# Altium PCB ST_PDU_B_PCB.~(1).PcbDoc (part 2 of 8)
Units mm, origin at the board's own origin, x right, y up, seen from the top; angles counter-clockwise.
Board outline 200 x 200 mm, 6 copper layers (Top Layer, Layer 1, Layer 2, Layer 3, Layer 4, Bottom Layer), stack 3.194 mm thick; 894 components, 723 nets, 3233 pads, 4067 vias.
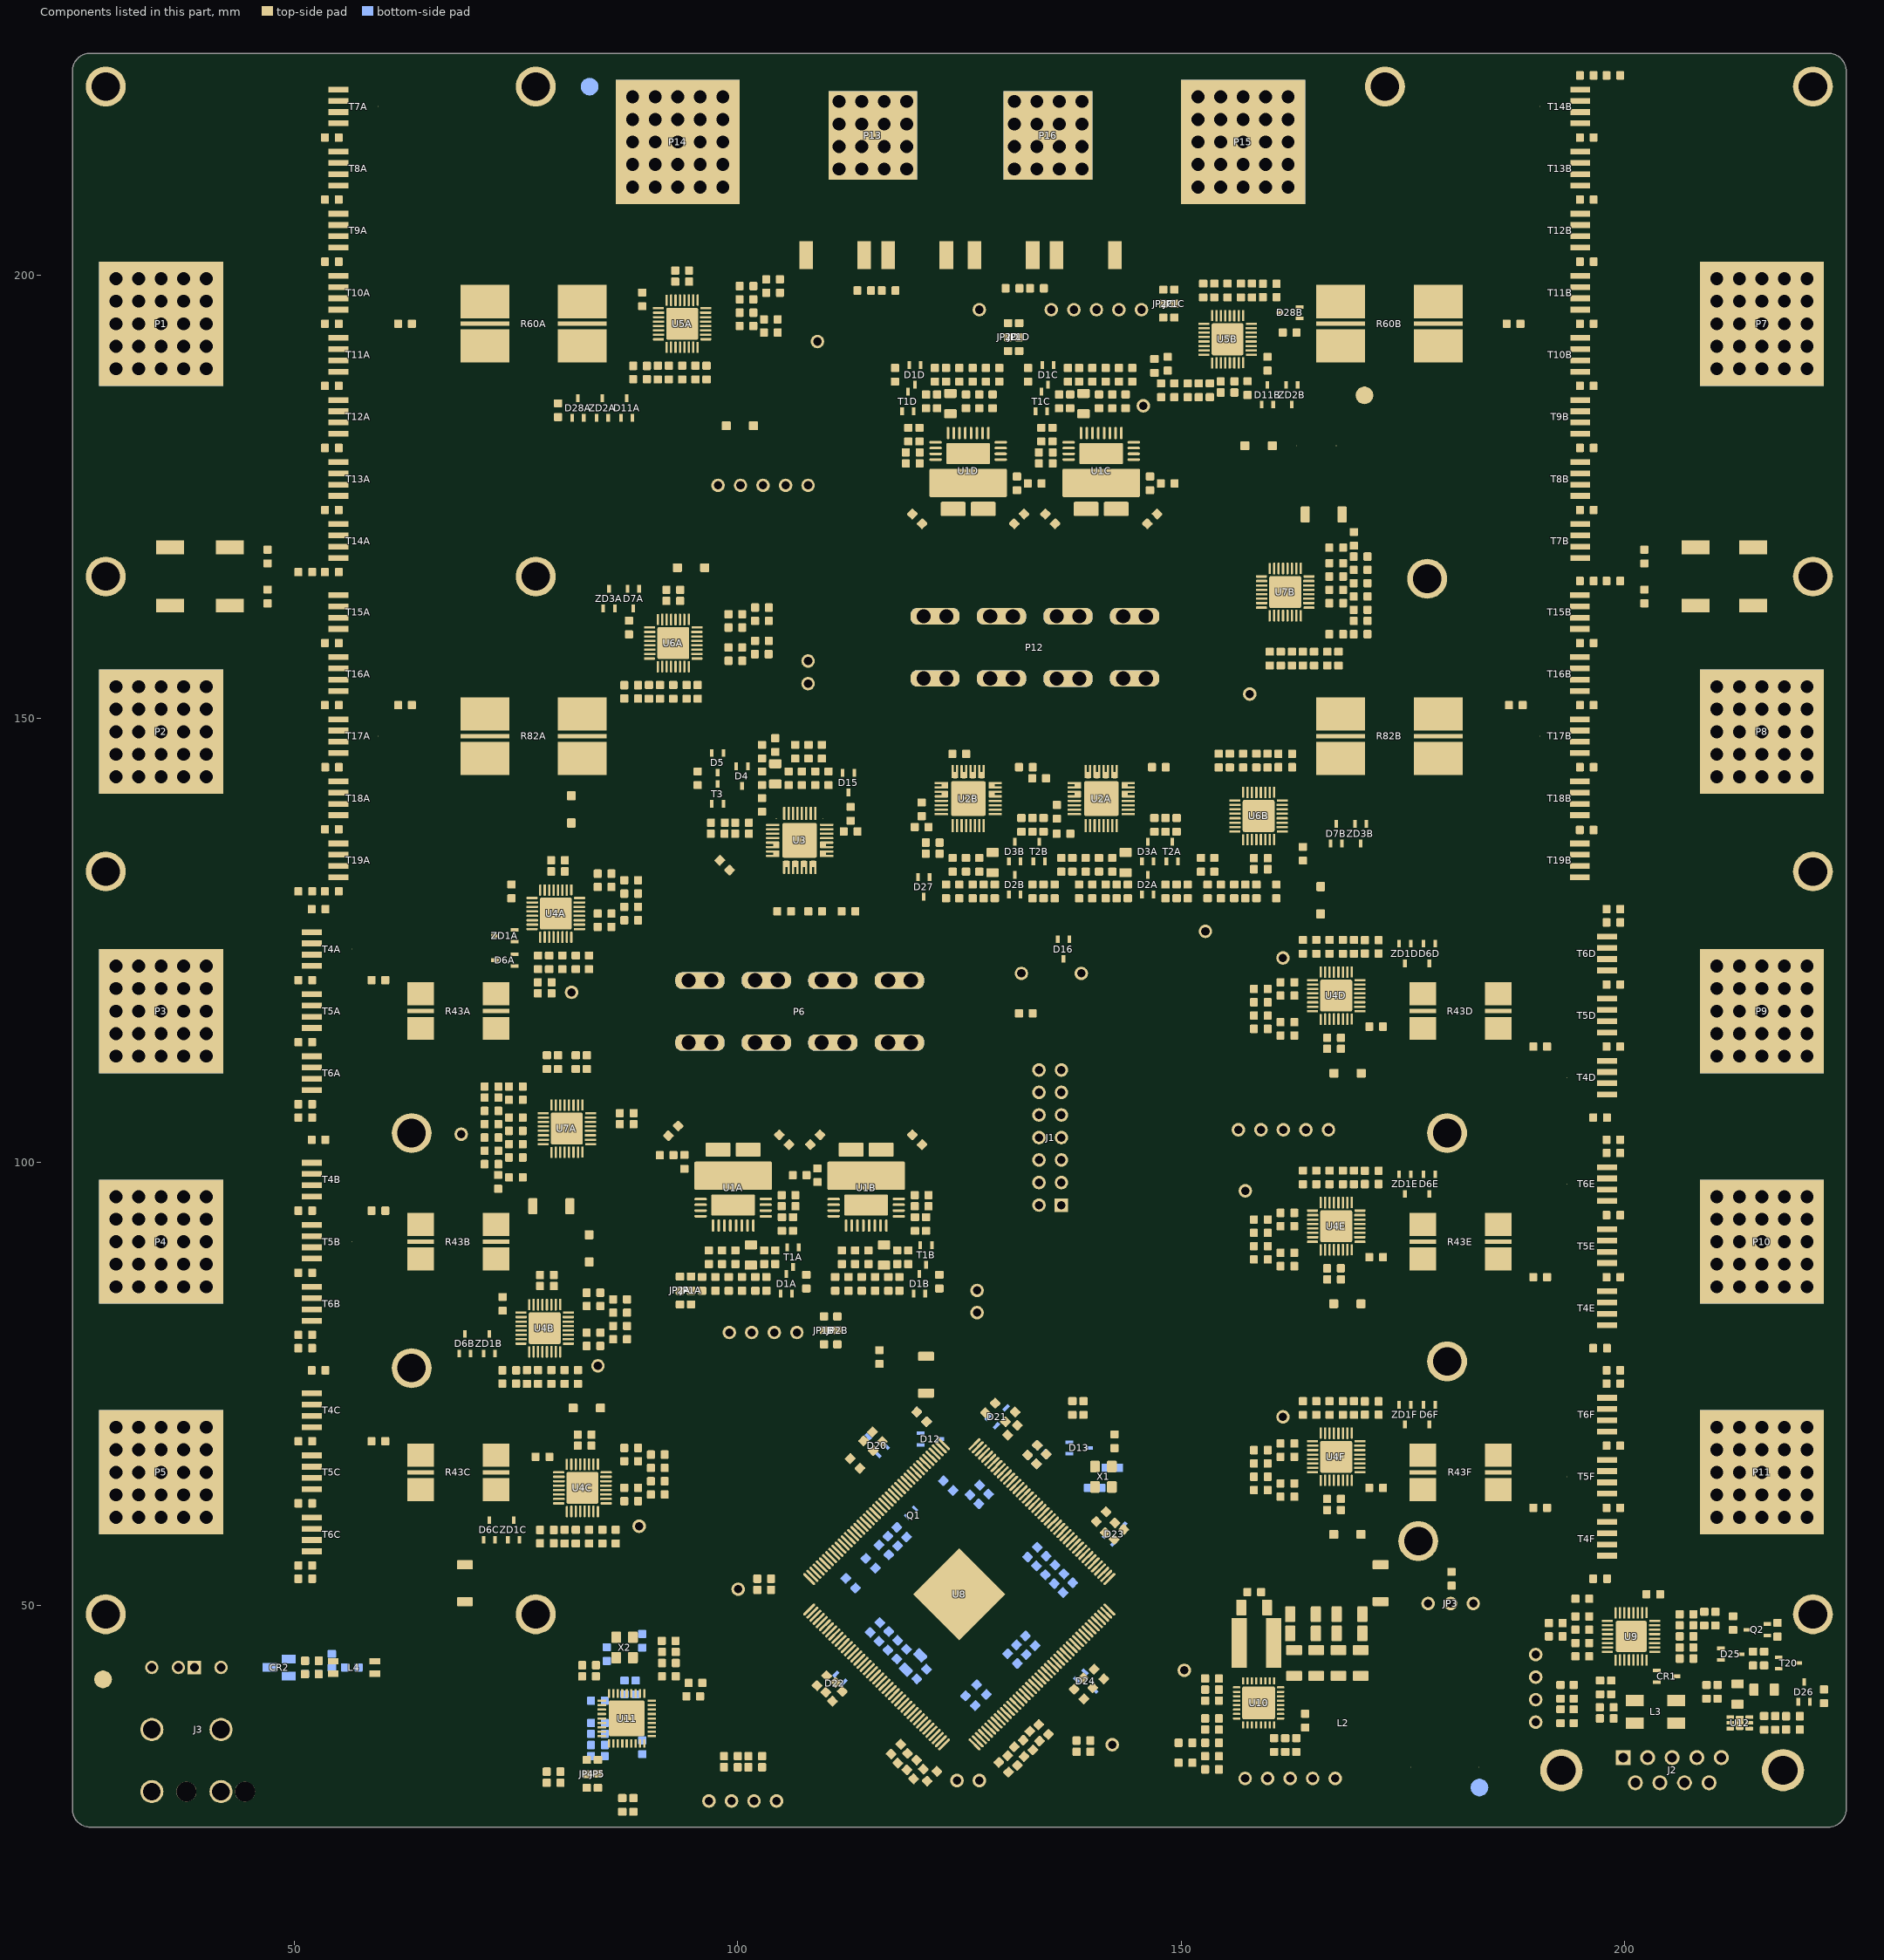
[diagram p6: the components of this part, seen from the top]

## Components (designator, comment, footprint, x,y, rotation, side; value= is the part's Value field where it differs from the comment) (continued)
R48D "2k7" R0603_round 162,120.25 r180 top (schematic designator R48)
R48E "2k7" R0603_round 162,94.25 r180 top (schematic designator R48)
R48F "2k7" R0603_round 162,68.25 r180 top (schematic designator R48)
R49A "5k6" R0603_round 88,127.25 r0 top (schematic designator R49)
R49B "5k6" R0603_round 86.75,80 r0 top (schematic designator R49)
R49C "5k6" R0603_round 91,62.5 r0 top (schematic designator R49)
R49D "5k6" R0603_round 159,119.5 r180 top (schematic designator R49)
R49E "5k6" R0603_round 159,93.5 r180 top (schematic designator R49)
R49F "5k6" R0603_round 159,67.5 r180 top (schematic designator R49)
R50A "180R" R0603_round 85,128 r180 top (schematic designator R50)
R50B "180R" R0603_round 83.75,80.75 r180 top (schematic designator R50)
R50C "180R" R0603_round 88,63.25 r180 top (schematic designator R50)
R50D "180R" R0603_round 162,118.75 r0 top (schematic designator R50)
R50E "180R" R0603_round 162,92.75 r0 top (schematic designator R50)
R50F "180R" R0603_round 162,66.75 r0 top (schematic designator R50)
R51A "5k6" R0603_round 88,128.75 r0 top (schematic designator R51)
R51B "5k6" R0603_round 86.75,81.5 r0 top (schematic designator R51)
R51C "5k6" R0603_round 91,64 r0 top (schematic designator R51)
R51D "5k6" R0603_round 159,118 r180 top (schematic designator R51)
R51E "5k6" R0603_round 159,92 r180 top (schematic designator R51)
R51F "5k6" R0603_round 159,66 r180 top (schematic designator R51)
R52 "15k" R0603_round 150.5,32.25 r180 top
R53A "1R" R0603_round 51.25,106.5 r180 top (schematic designator R53)
R53B "1R" R0603_round 51.25,80.5 r180 top (schematic designator R53)
R53C "1R" R0603_round 51.25,54.5 r180 top (schematic designator R53)
R53D "1R" R0603_round 198.75,127 r0 top (schematic designator R53)
R53E "1R" R0603_round 198.75,101 r0 top (schematic designator R53)
R53F "1R" R0603_round 198.75,75 r0 top (schematic designator R53)
R54A "NTC" R0603_round 59.5,120.5 r180 top value="NTC, 10K" (schematic designator R54)
R54B "NTC" R0603_round 59.5,94.5 r180 top value="NTC, 10K" (schematic designator R54)
R54C "NTC" R0603_round 59.5,68.5 r180 top value="NTC, 10K" (schematic designator R54)
R54D "NTC" R0603_round 190.5,113 r0 top value="NTC, 10K" (schematic designator R54)
R54E "NTC" R0603_round 190.5,87 r0 top value="NTC, 10K" (schematic designator R54)
R54F "NTC" R0603_round 190.5,61 r0 top value="NTC, 10K" (schematic designator R54)
R55A "47k" R0603_round 85,131 r180 top (schematic designator R55)
R55B "47k" R0603_round 83.75,83.75 r180 top (schematic designator R55)
R55C "47k" R0603_round 88,66.25 r180 top (schematic designator R55)
R55D "47k" R0603_round 162,115.75 r0 top (schematic designator R55)
R55E "47k" R0603_round 162,89.75 r0 top (schematic designator R55)
R55F "47k" R0603_round 162,63.75 r0 top (schematic designator R55)
R56A "10k" R0603_round 74.5,130.5 r270 top (schematic designator R56)
R56B "10k" R0603_round 73.5,84 r270 top (schematic designator R56)
R56C "10k" R0603_round 78,66.75 r180 top (schematic designator R56)
R56D "10k" R0603_round 172,115.25 r0 top (schematic designator R56)
R56E "10k" R0603_round 172,89.25 r0 top (schematic designator R56)
R56F "10k" R0603_round 172,63.25 r0 top (schematic designator R56)
R57A "2k7" R0603_round 88,130.25 r0 top (schematic designator R57)
R57B "2k7" R0603_round 86.75,83 r0 top (schematic designator R57)
R57C "2k7" R0603_round 91,65.5 r0 top (schematic designator R57)
R57D "2k7" R0603_round 159,116.5 r180 top (schematic designator R57)
R57E "2k7" R0603_round 159,90.5 r180 top (schematic designator R57)
R57F "2k7" R0603_round 159,64.5 r180 top (schematic designator R57)
R58A "2k7" R0603_round 88,131.75 r0 top (schematic designator R58)
R58B "2k7" R0603_round 86.75,84.5 r0 top (schematic designator R58)
R58C "2k7" R0603_round 91,67 r0 top (schematic designator R58)
R58D "2k7" R0603_round 159,115 r180 top (schematic designator R58)
R58E "2k7" R0603_round 159,89 r180 top (schematic designator R58)
R58F "2k7" R0603_round 159,63 r180 top (schematic designator R58)
R59A "2k7" R0603_round 85,132.5 r0 top (schematic designator R59)
R59B "2k7" R0603_round 83.75,85.25 r0 top (schematic designator R59)
R59C "2k7" R0603_round 88,67.75 r0 top (schematic designator R59)
R59D "2k7" R0603_round 162,114.25 r180 top (schematic designator R59)
R59E "2k7" R0603_round 162,88.25 r180 top (schematic designator R59)
R59F "2k7" R0603_round 162,62.25 r180 top (schematic designator R59)
R60A "0R0001" "R Shunt 5930" 77,194.5 r0 top (schematic designator R60)
R60B "0R0001" "R Shunt 5930" 173.5,194.5 r180 top (schematic designator R60)
R61A "1R" R0603_round 54.25,215.5 r180 top (schematic designator R61)
R61B "1R" R0603_round 195.75,173.5 r0 top (schematic designator R61)
R62A "1R" R0603_round 54.25,208.5 r180 top (schematic designator R62)
R62B "1R" R0603_round 195.75,180.5 r0 top (schematic designator R62)
R63A "1R" R0603_round 54.25,201.5 r180 top (schematic designator R63)
R63B "1R" R0603_round 195.75,187.5 r0 top (schematic designator R63)
R64A "47k" R0603_round 51.25,166.5 r180 top (schematic designator R64)
R64B "47k" R0603_round 198.75,222.5 r0 top (schematic designator R64)
R65 "15k" R0603_round 153.5,31.5 r180 top
R66A "1R" R0603_round 54.25,194.5 r180 top (schematic designator R66)
R66B "1R" R0603_round 195.75,194.5 r0 top (schematic designator R66)
R67A "2k7" R0603_round 103.75,193.5 r0 top (schematic designator R67)
R67B "2k7" R0603_round 147,189.75 r270 top (schematic designator R67)
R68A "5k6" R0603_round 101,194.25 r0 top (schematic designator R68)
R68B "5k6" R0603_round 147.75,187 r270 top (schematic designator R68)
R69A "180R" R0603_round 103.75,195 r180 top (schematic designator R69)
R69B "180R" R0603_round 148.5,190 r90 top (schematic designator R69)
R70A "5k6" R0603_round 101,195.75 r0 top (schematic designator R70)
R70B "5k6" R0603_round 149.25,187 r270 top (schematic designator R70)
R71 "0R" R0603_round 180.5,53 r270 top
R72A "1R" R0603_round 54.25,187.5 r180 top (schematic designator R72)
R72B "1R" R0603_round 195.75,201.5 r0 top (schematic designator R72)
R73A "NTC" R0603_round 62.5,194.5 r180 top value="NTC, 10K" (schematic designator R73)
R73B "NTC" R0603_round 187.5,194.5 r0 top value="NTC, 10K" (schematic designator R73)
R74A "1R" R0603_round 54.25,180.5 r180 top (schematic designator R74)
R74B "1R" R0603_round 195.75,208.5 r0 top (schematic designator R74)
R75A "47k" R0603_round 101,198.75 r180 top (schematic designator R75)
R75B "47k" R0603_round 152,187 r90 top (schematic designator R75)
R76A "10k" R0603_round 89.25,197.25 r270 top (schematic designator R76)
R76B "10k" R0603_round 159.75,190 r90 top (schematic designator R76)
R77A "2k7" R0603_round 101,197.25 r0 top (schematic designator R77)
R77B "2k7" R0603_round 150.75,187 r270 top (schematic designator R77)
R78A "2k7" R0603_round 104,198 r0 top (schematic designator R78)
R78B "2k7" R0603_round 153.25,187 r270 top (schematic designator R78)
R79A "1R" R0603_round 54.25,173.5 r180 top (schematic designator R79)
R79B "1R" R0603_round 195.75,215.5 r0 top (schematic designator R79)
R80A "2k7" R0603_round 104,199.5 r0 top (schematic designator R80)
R80B "2k7" R0603_round 157.5,187.25 r270 top (schematic designator R80)
R81A "1R" R0603_round 54.25,166.5 r180 top (schematic designator R81)
R81B "1R" R0603_round 195.75,222.5 r0 top (schematic designator R81)
R82A "0R0002" "R Shunt 5930" 77,148 r0 top (schematic designator R82)
R82B "0R0002" "R Shunt 5930" 173.5,148 r180 top (schematic designator R82)
R83A "1R" R0603_round 54.25,158.5 r180 top (schematic designator R83)
R83B "1R" R0603_round 195.75,165.5 r0 top (schematic designator R83)
R84A "47k" R0603_round 51.25,130.5 r180 top (schematic designator R84)
R84B "47k" R0603_round 198.75,165.5 r0 top (schematic designator R84)
R85 "10k" R0603_round 203.25,51.25 r0 top
R86A "1R" R0603_round 54.25,151.5 r180 top (schematic designator R86)
R86B "1R" R0603_round 195.75,158.5 r0 top (schematic designator R86)
R87A "2k7" R0603_round 99.75,156.5 r0 top (schematic designator R87)
R87B "2k7" R0603_round 152.25,133.5 r270 top (schematic designator R87)
R88A "5k6" R0603_round 102.725,157.25 r0 top (schematic designator R88)
R88B "5k6" R0603_round 153,130.5 r270 top (schematic designator R88)
R89A "180R" R0603_round 99.75,158 r180 top (schematic designator R89)
R89B "180R" R0603_round 153.75,133.5 r90 top (schematic designator R89)
R90A "5k6" R0603_round 102.75,158.75 r0 top (schematic designator R90)
R90B "5k6" R0603_round 154.5,130.5 r270 top (schematic designator R90)
R91 "10k" R0603_round 160.5,34.25 r90 top
R92A "1R" R0603_round 54.275,144.5 r180 top (schematic designator R92)
R92B "1R" R0603_round 195.75,151.5 r0 top (schematic designator R92)
R93A "NTC" R0603_round 62.5,151.5 r180 top value="NTC, 10K" (schematic designator R93)
R93B "NTC" R0603_round 187.75,151.5 r0 top value="NTC, 10K" (schematic designator R93)
R94A "47k" R0603_round 99.75,161.75 r180 top (schematic designator R94)
R94B "47k" R0603_round 158.5,130.5 r90 top (schematic designator R94)
R95A "1R" R0603_round 54.25,137.5 r180 top (schematic designator R95)
R95B "1R" R0603_round 195.75,144.5 r0 top (schematic designator R95)
R96A "10k" R0603_round 87.75,160.25 r270 top (schematic designator R96)
R96B "10k" R0603_round 163.749,134.749 r90 top (schematic designator R96)
R97A "2k7" R0603_round 99.75,160.25 r0 top (schematic designator R97)
R97B "2k7" R0603_round 156,130.5 r270 top (schematic designator R97)
R98A "2k7" R0603_round 102.75,161 r0 top (schematic designator R98)
R98B "2k7" R0603_round 157.25,130.5 r270 top (schematic designator R98)
R99A "2k7" R0603_round 102.75,162.5 r0 top (schematic designator R99)
R99B "2k7" R0603_round 160.75,130.5 r270 top (schematic designator R99)
R100A "1R" R0603_round 54.25,130.5 r180 top (schematic designator R100)
R100B "1R" R0603_round 195.736,137.423 r0 top (schematic designator R100)
R101A "330R" R0603_round 72.25,108.5 r180 top (schematic designator R101)
R101B "330R" R0603_round 170.25,159.5 r0 top (schematic designator R101)
R102A "2k7" R0603_round 75,107 r180 top (schematic designator R102)
R102B "2k7" R0603_round 165,156.75 r270 top (schematic designator R102)
R103A "2k7" R0603_round 75,102 r180 top (schematic designator R103)
R103B "2k7" R0603_round 167.5,166 r0 top (schematic designator R103)
R104A "2k7" R0603_round 72.25,101.25 r180 top (schematic designator R104)
R104B "2k7" R0603_round 170.25,166.75 r0 top (schematic designator R104)
R105A "2k7" R0603_round 75,100.5 r180 top (schematic designator R105)
R105B "2k7" R0603_round 167.5,167.5 r0 top (schematic designator R105)
R106A "2k7" R0603_round 72.25,99.75 r180 top (schematic designator R106)
R106B "2k7" R0603_round 170.25,168.25 r0 top (schematic designator R106)
R107A "2k7" R0603_round 75,105 r180 top (schematic designator R107)
R107B "2k7" R0603_round 167.5,163 r0 top (schematic designator R107)
R108A "5k6" R0603_round 72.25,102.75 r180 top (schematic designator R108)
R108B "5k6" R0603_round 170.25,165.25 r0 top (schematic designator R108)
R109A "5k6" R0603_round 72.25,104.25 r180 top (schematic designator R109)
R109B "5k6" R0603_round 170.25,163.75 r0 top (schematic designator R109)
R110A "180R" R0603_round 75,103.5 r180 top (schematic designator R110)
R110B "180R" R0603_round 167.5,164.5 r0 top (schematic designator R110)
R111 "0R" R0603_round 83,111.25 r270 top
R112 "0R" R0603_round 81.75,111.25 r270 top
R113 "0R" R0603_round 79.75,111.25 r270 top
R114 "0R" R0603_round 78.5,111.25 r270 top
R115 "0R" R0603_round 160,156.75 r90 top
R116 "0R" R0603_round 161.25,156.75 r90 top
R117 "0R" R0603_round 162.5,156.75 r90 top
R118 "0R" R0603_round 163.75,156.75 r90 top
R119 "47R" R0603_round 113.25,66 r135 top
R120 "47R" R0603_round 114.75,68 r135 top
R121 "47R" R0603_round 115.75,69 r135 top
R122 "47k" R0603_round 120.75,71.25 r135 bottom
R123 "15k" R0603_round 120.75,71.25 r135 top
R124 "47R" R0603_round 128.5,72.25 r45 top
R125 "47R" R0603_round 130.75,71.25 r45 top
R126 "47R" R0603_round 131,69.75 r45 top
R127 "4k7" R0603_round 133.25,67.5 r45 bottom
R128 "47k" R0603_round 134.239,66.511 r45 bottom
R129 "15k" R0603_round 133.25,67.5 r45 top
R130 "15k" R0603_round 134.25,66.5 r45 top
R131 "47R" R0603_round 109.5,41.5 r45 top
R132 "47R" R0603_round 110.5,40.75 r45 top
R133 "47R" R0603_round 111.25,39.75 r45 top
R134 "10k" R0603_round 132.5,116.75 r0 top
R135 "47R" R0603_round 141,60 r45 top
R136 "47R" R0603_round 142,58.75 r45 top
R137 "47R" R0603_round 143,58 r45 top
R138 "1K5" R0603_round 139,34.75 r0 top
R139 "47R" R0603_round 138.5,40 r315 top
R140 "47R" R0603_round 139.5,41.25 r315 top
R141 "47R" R0603_round 140.75,42.25 r315 top
R142 "1K5" R0603_round 103,51.75 r180 top
R143 "100k" R0603_round 131,32.5 r135 top
R144 "100k" R0603_round 118.618,32.766 r45 top
R145 "100k" R0603_round 133.5,35.25 r135 top
R146 "15k" R0603_round 131.75,33.5 r135 top
R147 "15k" R0603_round 117.856,33.782 r45 top
R148 "15k" R0603_round 134.5,36 r135 top
R149 "15k" R0603_round 130,31.75 r135 top
R150 "15k" R0603_round 119.634,32.004 r45 top
R151 "15k" R0603_round 132.75,34.25 r135 top
R152 "100R" R0603_round 195.25,50.75 r180 top
R153 "100R" R0603_round 195.25,48.75 r0 top
R154 "4k7" R0603_round 192.25,48 r0 top
R155 "180R" R0603_round 195.25,47.25 r0 top
R156 "2k7" R0603_round 163,34.25 r90 top
R157 "4k7" R0603_round 192.25,46.5 r0 top
R158 "3k3" R0603_round 153.5,36 r180 top
R159 "2k7" R0603_round 195.25,45.75 r180 top
R160 "15k" R0603_round 207,45.25 r0 top
R161 "15k" R0603_round 207,44 r0 top
R162 "2k7" R0603_round 153.5,41.75 r180 top
R163 "4k7" R0603_round 153.5,40.5 r0 top
R164 "4k7" R0603_round 153.5,39.25 r0 top
R165 "180R" R0603_round 153.5,37.25 r0 top
R166 "47k" R0603_round 161.75,34.25 r270 top
R167 "3k3" R0603_round 153.5,34.5 r0 top
R168 "3k3" R0603_round 150.5,34.5 r180 top
R169 "15k" R0603_round 121.92,30.734 r45 top
R170 "47k" R0603_round 212.25,48 r270 top
R171 "47k" R0603_round 215.75,44 r90 top
R172 "10k" R0603_round 214.5,44 r90 top
R173 "47k" R0603_round 217.25,47.25 r90 top
R174 "47k" R0603_round 88.25,27.5 r90 top
R175 "47k" R0603_round 87,27.5 r90 top
R176 "47k" R0603_round 79.25,31.25 r0 top
R177 "1k" R0603_round 52,43.75 r0 bottom
R178 "1k" R0603_round 52,42.25 r0 bottom
R179 "47k" R0603_round 120.396,30.988 r45 top
R180 "47k" R0603_round 79.25,30 r0 top
R181 "10k" R0603_round 95,39.75 r0 top
R182 "47k" R0603_round 92.25,44.75 r180 top
R183 "100k" R0603_round 56.5,43 r180 bottom
R184 "47R" R0603_round 92.25,42 r180 top
R185 "15k" R0603_round 95.25,41.25 r180 top
R186 "15k" R0603_round 92.25,43.5 r180 top
R187 "1k" R0603_round 83.25,43.25 r180 top
R188 "15k" R0603_round 92.225,46 r180 top
R189 "30k" R0603_round 88.5,40.75 r90 bottom
R190 "10k" R0603_round 114.275,198.25 r180 top
R191 "10k" R0603_round 133.75,198.5 r0 top
R192 "4k7" R0603_round 194.286,40.25 r270 top
R193 "2k7" R0603_round 192.786,40.25 r90 top
R194 "2k7" R0603_round 210.5,40.25 r90 top
R195 "2k7" R0603_round 99.242,31.75 r180 top
R196 "2k7" R0603_round 101.992,31.75 r0 top
R197A "0R" R0603_round 72.25,105.75 r180 top (schematic designator R197)
R197B "0R" R0603_round 170.25,162.25 r0 top (schematic designator R197)
R198A "0R" R0603_round 87.5,105.5 r0 top (schematic designator R198)
R198B "0R" R0603_round 167.75,156.75 r270 top (schematic designator R198)
R199 "360k" R0603_round 219,37.5 r0 top
R200 "200k" R0603_round 215.75,36.75 r90 top
R201 "200k" R0603_round 219,36 r0 top
R202 "1K5" R0603_round 139,72.25 r270 top
R203 "47k" R0603_round 222.5,39.75 r90 top
R204 "47R" R0603_round 116,78 r90 top
R205 "47R" R0603_round 142.5,68.5 r90 top
R206A "47R" R0603_round 79.75,184.75 r270 top (schematic designator R206)
R206B "47R" R0603_round 162.25,193.5 r0 top (schematic designator R206)
T1A "BC847" SOT323-3L_STM 106.25,89.25 r270 top (schematic designator T1)
T1B "BC847" SOT323-3L_STM 121.25,89.5 r270 top (schematic designator T1)
T1C "BC847" SOT323-3L_STM 134.25,185.75 r90 top (schematic designator T1)
T1D "BC847" SOT323-3L_STM 119.2,185.75 r90 top (schematic designator T1)
T2A "BC847" SOT323-3L_STM 149,135 r90 top (schematic designator T2)
T2B "BC847" SOT323-3L_STM 134,135 r90 top (schematic designator T2)
T3 "BC847" SOT323-3L_STM 97.75,141.5 r90 top
T4A "NMOS" Powerflat_5x6_Single_island 54,124 r0 top value=STL059N4S8AG (schematic designator T4)
T4B "NMOS" Powerflat_5x6_Single_island 54,98 r0 top value=STL059N4S8AG (schematic designator T4)
T4C "NMOS" Powerflat_5x6_Single_island 54,72 r0 top value=STL059N4S8AG (schematic designator T4)
T4D "NMOS" Powerflat_5x6_Single_island 196,109.5 r180 top value=STL059N4S8AG (schematic designator T4)
T4E "NMOS" Powerflat_5x6_Single_island 196,83.5 r180 top value=STL059N4S8AG (schematic designator T4)
T4F "NMOS" Powerflat_5x6_Single_island 196,57.5 r180 top value=STL059N4S8AG (schematic designator T4)
T5A "NMOS" Powerflat_5x6_Single_island 54,117 r0 top value=STL059N4S8AG (schematic designator T5)
T5B "NMOS" Powerflat_5x6_Single_island 54,91 r0 top value=STL059N4S8AG (schematic designator T5)
T5C "NMOS" Powerflat_5x6_Single_island 54,65 r0 top value=STL059N4S8AG (schematic designator T5)
T5D "NMOS" Powerflat_5x6_Single_island 196,116.5 r180 top value=STL059N4S8AG (schematic designator T5)
T5E "NMOS" Powerflat_5x6_Single_island 196,90.5 r180 top value=STL059N4S8AG (schematic designator T5)
T5F "NMOS" Powerflat_5x6_Single_island 196,64.5 r180 top value=STL059N4S8AG (schematic designator T5)
T6A "NMOS" Powerflat_5x6_Single_island 54,110 r0 top value=STL059N4S8AG (schematic designator T6)
T6B "NMOS" Powerflat_5x6_Single_island 54,84 r0 top value=STL059N4S8AG (schematic designator T6)
T6C "NMOS" Powerflat_5x6_Single_island 54,58 r0 top value=STL059N4S8AG (schematic designator T6)
T6D "NMOS" Powerflat_5x6_Single_island 196,123.5 r180 top value=STL059N4S8AG (schematic designator T6)
T6E "NMOS" Powerflat_5x6_Single_island 196,97.5 r180 top value=STL059N4S8AG (schematic designator T6)
T6F "NMOS" Powerflat_5x6_Single_island 196,71.5 r180 top value=STL059N4S8AG (schematic designator T6)
T7A "NMOS" Powerflat_5x6_Single_island 57,219 r0 top value=STL059N4S8AG (schematic designator T7)
T7B "NMOS" Powerflat_5x6_Single_island 193,170 r180 top value=STL059N4S8AG (schematic designator T7)
T8A "NMOS" Powerflat_5x6_Single_island 57,212 r0 top value=STL059N4S8AG (schematic designator T8)
T8B "NMOS" Powerflat_5x6_Single_island 193,177 r180 top value=STL059N4S8AG (schematic designator T8)
T9A "NMOS" Powerflat_5x6_Single_island 57,205 r0 top value=STL059N4S8AG (schematic designator T9)
T9B "NMOS" Powerflat_5x6_Single_island 193,184 r180 top value=STL059N4S8AG (schematic designator T9)
T10A "NMOS" Powerflat_5x6_Single_island 57,198 r0 top value=STL059N4S8AG (schematic designator T10)
T10B "NMOS" Powerflat_5x6_Single_island 193,191 r180 top value=STL059N4S8AG (schematic designator T10)
T11A "NMOS" Powerflat_5x6_Single_island 57,191 r0 top value=STL059N4S8AG (schematic designator T11)
T11B "NMOS" Powerflat_5x6_Single_island 193,198 r180 top value=STL059N4S8AG (schematic designator T11)
T12A "NMOS" Powerflat_5x6_Single_island 57,184 r0 top value=STL059N4S8AG (schematic designator T12)
T12B "NMOS" Powerflat_5x6_Single_island 193,205 r180 top value=STL059N4S8AG (schematic designator T12)
T13A "NMOS" Powerflat_5x6_Single_island 57,177 r0 top value=STL059N4S8AG (schematic designator T13)
T13B "NMOS" Powerflat_5x6_Single_island 193,212 r180 top value=STL059N4S8AG (schematic designator T13)
T14A "NMOS" Powerflat_5x6_Single_island 57,170 r0 top value=STL059N4S8AG (schematic designator T14)
T14B "NMOS" Powerflat_5x6_Single_island 193,219 r180 top value=STL059N4S8AG (schematic designator T14)
T15A "NMOS" Powerflat_5x6_Single_island 57,162 r0 top value=STL059N4S8AG (schematic designator T15)
T15B "NMOS" Powerflat_5x6_Single_island 192.95,162 r180 top value=STL059N4S8AG (schematic designator T15)
T16A "NMOS" Powerflat_5x6_Single_island 57,155 r0 top value=STL059N4S8AG (schematic designator T16)
T16B "NMOS" Powerflat_5x6_Single_island 192.95,155 r180 top value=STL059N4S8AG (schematic designator T16)
T17A "NMOS" Powerflat_5x6_Single_island 57,148 r0 top value=STL059N4S8AG (schematic designator T17)
T17B "NMOS" Powerflat_5x6_Single_island 192.95,148 r180 top value=STL059N4S8AG (schematic designator T17)
T18A "NMOS" Powerflat_5x6_Single_island 57,141 r0 top value=STL059N4S8AG (schematic designator T18)
T18B "NMOS" Powerflat_5x6_Single_island 192.95,141 r180 top value=STL059N4S8AG (schematic designator T18)
T19A "NMOS" Powerflat_5x6_Single_island 57,134 r0 top value=STL059N4S8AG (schematic designator T19)
T19B "NMOS" Powerflat_5x6_Single_island 192.95,134 r180 top value=STL059N4S8AG (schematic designator T19)
T20 "BC857" SOT323-3L_STM 218.5,43.5 r0 top
TP1 "TX" PIN 99.314,27.94 r90 top value=UART_TX
TP2 "RX" PIN 101.854,27.94 r90 top value=UART_RX
TP3 "3V3" PIN 104.394,27.94 r90 top value=UART_3V3
TP4 "SPI5_CS6" PIN 127.254,196.088 r90 top value=SPI2_MOSI
TP5 "5V" PIN 189.992,39.37 r0 top
TP6 "3V3" PIN 189.992,41.91 r0 top
TP7 "GND" PIN 189.992,36.83 r0 top
TP8 "GND" PIN 96.774,27.94 r0 top
TP9 "CS0" PIN 145.542,196.088 r90 top value=SPI2_MOSI
TP10 "GND" PIN 100.33,176.276 r0 top
TP11 "GND" PIN 106.68,80.772 r0 top
TP12 "MOSI" PIN 105.41,176.276 r90 top value=SPI9_MOSI
TP13 "MISO" PIN 102.87,176.276 r90 top value=SPI9_MISO
TP14 "SCK" PIN 107.95,176.276 r90 top value=SPI9_SCK
TP15 "SPI9_CS5" PIN 88.9,58.928 r90 top
TP16 "SPI9_CS4" PIN 84.25,77 r90 top
TP17 "SPI9_CS2" PIN 81.28,119.126 r90 top
TP18 "SPI9_CS0" PIN 107.95,156.464 r90 top
TP19 "SPI9_CS1" PIN 109,192.5 r90 top
TP20 "SPI3_CS6" PIN 150.368,42.672 r90 top
TP21 "DIAG_A" PIN 97.79,176.276 r90 top
TP22 "GND" PIN 164.084,103.632 r0 top
TP23 "GND" PIN 135.382,196.088 r0 top
TP24 "MISO" PIN 104.14,80.772 r90 top value=SPI0_MISO
TP25 "SPI0_CS2" PIN 107.95,153.924 r90 top value=SPI0_CS6
TP26 "MOSI" PIN 101.6,80.772 r90 top value=SPI0_MOSI
TP27 "SCK" PIN 99.06,80.772 r90 top value=SPI0_SCK
TP28 "SPI0_CS6" PIN 127,85.5 r90 top value=SPI0_CS2
TP29 "SPI0_CS1" PIN 68.834,103.124 r90 top value=SPI0_CS6
TP30 "SPI0_CS0" PIN 127,83 r90 top value=SPI0_CS6
TP31 "RST" PIN 157.226,30.48 r0 top
TP32 "DIAG_B" PIN 166.624,103.632 r90 top
TP33 "MISO" PIN 162.306,30.48 r270 top value=SPI3_MISO
TP34 "MOSI" PIN 164.846,30.48 r270 top value=SPI3_MOSI
TP35 "SCK" PIN 167.386,30.48 r270 top value=SPI3_SCK
TP36 "SPI3_CS0" PIN 189.992,44.45 r90 top
TP37 "SCK" PIN 143.002,196.088 r90 top value=SPI5_SCK
TP38 "MISO" PIN 140.462,196.088 r90 top value=SPI5_MISO
TP39 "MOSI" PIN 137.922,196.088 r90 top value=SPI5_MOSI
TP40 "FAULT" PIN 142.24,34.29 r90 top
TP41 "TEST0" PIN 100.076,51.816 r90 top
TP42 "SPI2_CS2" PIN 161.5,71.25 r90 top
TP43 "SPI2_CS4" PIN 157.25,96.75 r90 top
TP44 "SPI2_CS3" PIN 161.5,123 r90 top
TP45 "SPI2_CS1" PIN 152.75,126 r90 top
TP46 "SPI2_CS0" PIN 145.75,185.25 r90 top
TP47 "MOSI" PIN 159.004,103.632 r90 top value=SPI2_MOSI
TP48 "SCK" PIN 156.464,103.632 r90 top value=SPI2_SCK
TP49 "MISO" PIN 161.544,103.632 r90 top value=SPI2_MISO
TP50 "GND" PIN 159.766,30.48 r0 top
TP51 "SPI5_CS3" PIN 157.75,152.75 r90 top
TP52 "SPI5_CS1" PIN 138.75,121.25 r90 top
TP53 "SPI5_CS5" PIN 132,121.25 r90 top
Tr_d3 "SM30T30A" SMC 36,166 r270 top
Tr_d4 "SM30T30A" SMC 42.75,166 r90 top
Tr_d10 "SM30T30A" SMC 208,166 r270 top
Tr_d13 "SM30T30A" SMC 214.5,166 r90 top
Tr_d18 "SM15T39A" SMC 111,202.25 r180 top
Tr_d19 "SM15T39A" SMC 139.25,202.25 r0 top
Tr_d20 "SM15T18A" SMC 120.25,202.25 r0 top
Tr_d21 "SM15T18A" SMC 130,202.25 r180 top
U1A "VNF9D1M5Q" "PQFN 7x8.5" 96,101.5 r0 top (schematic designator U1)
U1B "VNF9D1M5Q" "PQFN 7x8.5" 111,101.5 r0 top (schematic designator U1)
U1C "VNF9D1M5Q" "PQFN 7x8.5" 144.5,173.5 r180 top (schematic designator U1)
U1D "VNF9D1M5Q" "PQFN 7x8.5" 129.5,173.5 r180 top (schematic designator U1)
U2A "VNF9D5SF" QFN6x6_VN9D30_STM 141.013,140.965 r0 top (schematic designator U2)
U2B "VNF9D5SF" QFN6x6_VN9D30_STM 126.013,140.965 r0 top (schematic designator U2)
U3 "VNF9Q20SF" QFN6x6_VN9D30_STM 107,136.25 r180 top
U4A "VNF1248F" QFN32L_5x5_STM-M#1 79.5,128 r180 top (schematic designator U4)
U4B "VNF1248F" QFN32L_5x5_STM-M#1 78.25,81.25 r180 top (schematic designator U4)
U4C "VNF1248F" QFN32L_5x5_STM-M#1 82.5,63.25 r180 top (schematic designator U4)
U4D "VNF1248F" QFN32L_5x5_STM-M#1 167.5,118.75 r0 top (schematic designator U4)
U4E "VNF1248F" QFN32L_5x5_STM-M#1 167.5,92.75 r0 top (schematic designator U4)
U4F "VNF1248F" QFN32L_5x5_STM-M#1 167.5,66.75 r0 top (schematic designator U4)
U5A "VNF1248F" QFN32L_5x5_STM-M#1 93.75,194.5 r180 top (schematic designator U5)
U5B "VNF1248F" QFN32L_5x5_STM-M#1 155.25,192.75 r0 top (schematic designator U5)
U6A "VNF1248F" QFN32L_5x5_STM-M#1 92.75,158.5 r180 top (schematic designator U6)
U6B "VNF1248F" QFN32L_5x5_STM-M#1 158.75,139 r0 top (schematic designator U6)
U7A "L99SP08" QFN32L_5x5_STM-M#1 80.75,103.75 r0 top (schematic designator U7)
U7B "L99SP08" QFN32L_5x5_STM-M#1 161.75,164.25 r180 top (schematic designator U7)
U8 "SPC58NG84E7" "eLQFP176 (LQFP176L2600X2600-176)" 125,51.25 r45 top
U9 "SPSB0813" QFN32L_5x5_STM-M#2 200.75,46.5 r180 top
U10 "SPSA068" QFN32_5X5MM_STM 158.75,39 r270 top
U11 "TJA1101" HVQFN36_SOT1092-2DD_NXP 87.5,37.25 r270 top
U12 "LDL40PURY" DFN6_2X2_STM 213,36.75 r0 top
X1 "40MHz" CRYSTAL_SMD_3.2x2.5mm 141.25,64.5 r90 top value="40 MHz"
X2 "25MHz" CRYSTAL_SMD_3.2x2.5mm 87.25,45.25 r90 top
ZD1A "5,6V/SOT-323" SOT323-3L_STM 73.75,125.5 r180 top value=5,6V (schematic designator ZD1)
ZD1B "5,6V/SOT-323" SOT323-3L_STM 72,79.5 r90 top value=5,6V (schematic designator ZD1)
ZD1C "5,6V/SOT-323" SOT323-3L_STM 74.75,58.5 r90 top value=5,6V (schematic designator ZD1)
ZD1D "5,6V/SOT-323" SOT323-3L_STM 175.25,123.5 r270 top value=5,6V (schematic designator ZD1)
ZD1E "5,6V/SOT-323" SOT323-3L_STM 175.25,97.5 r270 top value=5,6V (schematic designator ZD1)
ZD1F "5,6V/SOT-323" SOT323-3L_STM 175.25,71.5 r270 top value=5,6V (schematic designator ZD1)
ZD2A "5,6V/SOT-323" SOT323-3L_STM 84.75,185 r90 top value=5,6V (schematic designator ZD2)
ZD2B "5,6V/SOT-323" SOT323-3L_STM 162.5,186.5 r270 top value=5,6V (schematic designator ZD2)
ZD3A "5,6V/SOT-323" SOT323-3L_STM 85.5,163.5 r90 top value=5,6V (schematic designator ZD3)
ZD3B "5,6V/SOT-323" SOT323-3L_STM 170.25,137 r270 top value=5,6V (schematic designator ZD3)

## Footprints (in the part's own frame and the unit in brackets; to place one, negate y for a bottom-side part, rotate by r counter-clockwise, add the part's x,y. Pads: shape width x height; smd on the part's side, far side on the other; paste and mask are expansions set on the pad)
"Broadreach connector - TE_2304372-2" [mm]
  rect 1.508x1.508 / inner rect 1x1 / far side rect 1.508x1.508 hole 1: 1(4.8,0)
  round 1.508 / inner round 1 / far side round 1.508 hole 1: 2(3,0)
  round 1.508 hole 1: S1(0,0) S2(7.8,0)
  round 2.6 hole 2: S3(0,-7) S4(7.8,-7) S5(0,-14) S6(7.8,-14)
  round 2.25 hole 2.25 unplated: ""(3.9,-14) ""(10.5,-14)
  silkscreen extent -3.55,-19.16 14.2,1.44, body extent -3.65,-19.23 14.1,1.87, height 13.1
C0603_ROUND [mm] "Capacitor 0603; Body 1.6 x 0.8 mm (LxW typ); IPC_7351 nominal"
  rrect25% 0.9x0.95 smd: 1(-0.775,0) 2(0.775,0)
  silkscreen extent -0.14,-0.51 0.14,0.51, body extent -0.8,-0.4 0.8,0.4, height 0.8
C0805_ROUND [mm]
  rrect25% 1.025x1.4 smd: 1(-1.143,0) 2(1.143,0)
  silkscreen extent -0.23,-0.73 0.23,0.73, body extent -1,-0.63 1,0.63, height 0.5
C1206_ROUND [mm]
  rrect25% 1.15x1.8 smd: 1(-1.45,0) 2(1.45,0)
  silkscreen extent -0.7,-0.92 0.7,0.92, body extent -1.6,-0.8 1.6,0.8, height 1
"C_EL 6.3x6.1mm VP" [mil] "Vibration proof electrolytic capacitor"
  round 1 smd: 1(88.58,0) 2(-88.58,0)
  Top Layer region: 49.21,62.99 49.21,23.62 23.62,23.62 23.62,-23.62 49.21,-23.62 49.21,-62.99 127.95,-62.99 127.95,-23.62 165.35,-23.62 165.35,23.62 127.95,23.62 127.95,62.99
  Top Layer region: -127.95,62.99 -127.95,23.62 -165.35,23.62 -165.35,-23.62 -127.95,-23.62 -127.95,-62.99 -49.21,-62.99 -49.21,-23.62 -23.62,-23.62 -23.62,23.62 -49.21,23.62 -49.21,62.99
  silkscreen extent -142,-138 193,138, body extent -144,-130 144,130, height 240
"C_EL 10x10.5mm VP" [mil] "Vibration proof electrolytic capacitor"
  round 1 smd: 1(149.61,0) 2(-149.61,0)
  Top Layer region: 175.2,-92.52 175.2,-49.21 250,-49.21 250,49.21 175.2,49.21 175.2,92.52 124.02,92.52 124.02,49.21 76.77,49.21 76.77,-49.21 124.02,-49.21 124.02,-92.52
  Top Layer region: -175.2,92.52 -175.2,49.21 -250,49.21 -250,-49.21 -175.2,-49.21 -175.2,-92.52 -124.02,-92.52 -124.02,-49.21 -76.77,-49.21 -76.77,49.21 -124.02,49.21 -124.02,92.52
  silkscreen extent -217,-213 287,213, body extent -230,-203 230,203, height 413
CAN_CMC [mil] "Common Mode Choke,4 Leads; Row Spacing 5mm ; Pitch 2.54 mm"
  rect 50x80 smd: 1(-50,-92.5) 2(-50,92.5) 3(50,92.5) 4(50,-92.5)
  silkscreen extent -86,-142 86,142, body extent -63,-85 63,85, height 118
CRYSTAL_SMD_3.2x2.5mm [mm] "per CX3225CA25000D0HSSZ1"
  rrect25% 1.3x1.1 smd: 1(1.15,0.95) 2(-1.15,0.95) 3(-1.15,-0.95) 4(1.15,-0.95)
  silkscreen extent -0.25,-1.5 2.1,1.85, body extent -1.6,-1.25 1.6,1.25, height 0.77
D0603_ROUND [mm] "Diode 0603; Body 1.6 x 0.8 mm (LxW typ); IPC_7351 nominal"
  rrect25% 0.9x0.95 smd: A(-0.775,0) C(0.775,0)
  silkscreen extent -0.14,-0.51 0.14,0.51, body extent -0.8,-0.4 0.8,0.4, height 0.8
DFN6_2X2_STM [mm]
  rrect25% 0.9x1.6 smd paste+0 mask+0: 0(0,0)
  rrect25% 0.85x0.4 smd paste+0 mask+0: 1(-1.075,0.65) 2(-1.075,0) 3(-1.075,-0.65) 4(1.075,-0.65) 5(1.075,0) 6(1.075,0.65)
  silkscreen extent -1.7,-1.13 1.13,1.13, body extent -1,-1 1,1, height 0.61
DFN2020-3 [mil]
  rrect25% 30x12 smd: 1(-38.5,25.59) 2(-38.5,-25.59)
  round 1 smd: 3(20.92,0)
  Top Layer region: -11.66,-29.68 -11.66,29.68 -11.52,30.38 -11.12,30.97 -10.53,31.36 -9.84,31.5 -9.84,31.5 29.52,31.5 30.22,31.36 30.81,30.97 31.2,30.38 31.34,29.68 31.34,29.68 31.34,6 52.07,6 52.62,5.89 53.08,5.58 53.39,5.12 53.5,4.57 53.5,4.57 53.5,-4.57 53.39,-5.12 53.08,-5.58 52.62,-5.89 52.07,-6 52.07,-6 31.34,-6 31.34,-29.68 31.2,-30.38 30.81,-30.97 30.22,-31.36 29.52,-31.5 29.52,-31.5 -9.84,-31.5 -10.53,-31.36 -11.12,-30.97 -11.52,-30.38 -11.66,-29.68
  silkscreen extent -69,-46 49,46, body extent -39,-39 40,39, height 25
DLW43_MUR [mm]
  rect 1.194x0.711 smd: 1(-2.35,0.7) 2(2.35,0.7) 3(2.35,-0.7) 4(-2.35,-0.7)
  silkscreen extent -3.01,-1.83 2.48,2.12, body extent -2.35,-1.7 2.35,1.7, height 2.64
DSUB_9M [mm] "Cannon Connector; Male - 9 Position; Right Angle; Pitch 1.385 mm"
  rect 1.69x1.69 hole 1.09: 1(5.54,-1.42)
  round 1.69 hole 1.09: 2(2.77,-1.42) 3(0,-1.42) 4(-2.77,-1.42) 5(-5.54,-1.42) 6(4.155,1.42) 7(1.385,1.42) 8(-1.385,1.42) 9(-4.155,1.42)
  round 4.76 hole 3.26: 10(12.495,0) 11(-12.495,0)
  silkscreen extent -15.4,-2.9 15.4,15.5, body extent -15.45,-3.58 15.35,17.02, height 13.77
"eLQFP176 (LQFP176L2600X2600-176)" [mm] "LQFP, 176-Leads, Body 24x24mm, Pitch 0.5mm, Exposed pad Down"
  rect 7.35x7.35 smd paste-2539.97: 0(0,0)
  oval 1.8x0.3 smd: 1(-13.185,10.75) 2(-13.185,10.25) 3(-13.185,9.75) 4(-13.185,9.25) 5(-13.185,8.75) 6(-13.185,8.25) 7(-13.185,7.75) 8(-13.185,7.25) 9(-13.185,6.75) 10(-13.185,6.25) 11(-13.185,5.75) 12(-13.185,5.25) 13(-13.185,4.75) 14(-13.185,4.25) 15(-13.185,3.75) 16(-13.185,3.25) 17(-13.185,2.75) 18(-13.185,2.25) 19(-13.185,1.75) 20(-13.185,1.25) 21(-13.185,0.75) 22(-13.185,0.25) 23(-13.185,-0.25) 24(-13.185,-0.75) 25(-13.185,-1.25) 26(-13.185,-1.75) 27(-13.185,-2.25) 28(-13.185,-2.75) 29(-13.185,-3.25) 30(-13.185,-3.75) 31(-13.185,-4.25) 32(-13.185,-4.75) 33(-13.185,-5.25) 34(-13.185,-5.75) 35(-13.185,-6.25) 36(-13.185,-6.75) 37(-13.185,-7.25) 38(-13.185,-7.75) 39(-13.185,-8.25) 40(-13.185,-8.75) 41(-13.185,-9.25) 42(-13.185,-9.75) 43(-13.185,-10.25) 44(-13.185,-10.75) 89(13.185,-10.75) 90(13.185,-10.25) 91(13.185,-9.75) 92(13.185,-9.25) 93(13.185,-8.75) 94(13.185,-8.25) 95(13.185,-7.75) 96(13.185,-7.25) 97(13.185,-6.75) 98(13.185,-6.25) 99(13.185,-5.75) 100(13.185,-5.25) 101(13.185,-4.75) 102(13.185,-4.25) 103(13.185,-3.75) 104(13.185,-3.25) 105(13.185,-2.75) 106(13.185,-2.25) 107(13.185,-1.75) 108(13.185,-1.25) 109(13.185,-0.75) 110(13.185,-0.25) 111(13.185,0.25) 112(13.185,0.75) 113(13.185,1.25) 114(13.185,1.75) 115(13.185,2.25) 116(13.185,2.75) 117(13.185,3.25) 118(13.185,3.75) 119(13.185,4.25) 120(13.185,4.75) 121(13.185,5.25) 122(13.185,5.75) 123(13.185,6.25) 124(13.185,6.75) 125(13.185,7.25) 126(13.185,7.75) 127(13.185,8.25) 128(13.185,8.75) 129(13.185,9.25) 130(13.185,9.75) 131(13.185,10.25) 132(13.185,10.75)
  oval 0.3x1.8 smd: 45(-10.75,-13.185) 46(-10.25,-13.185) 47(-9.75,-13.185) 48(-9.25,-13.185) 49(-8.75,-13.185) 50(-8.25,-13.185) 51(-7.75,-13.185) 52(-7.25,-13.185) 53(-6.75,-13.185) 54(-6.25,-13.185) 55(-5.75,-13.185) 56(-5.25,-13.185) 57(-4.75,-13.185) 58(-4.25,-13.185) 59(-3.75,-13.185) 60(-3.25,-13.185) 61(-2.75,-13.185) 62(-2.25,-13.185) 63(-1.75,-13.185) 64(-1.25,-13.185) 65(-0.75,-13.185) 66(-0.25,-13.185) 67(0.25,-13.185) 68(0.75,-13.185) 69(1.25,-13.185) 70(1.75,-13.185) 71(2.25,-13.185) 72(2.75,-13.185) 73(3.25,-13.185) 74(3.75,-13.185) 75(4.25,-13.185) 76(4.75,-13.185) 77(5.25,-13.185) 78(5.75,-13.185) 79(6.25,-13.185) 80(6.75,-13.185) 81(7.25,-13.185) 82(7.75,-13.185) 83(8.25,-13.185) 84(8.75,-13.185) 85(9.25,-13.185) 86(9.75,-13.185) 87(10.25,-13.185) 88(10.75,-13.185) 133(10.75,13.185) 134(10.25,13.185) 135(9.75,13.185) 136(9.25,13.185) 137(8.75,13.185) 138(8.25,13.185) 139(7.75,13.185) 140(7.25,13.185) 141(6.75,13.185) 142(6.25,13.185) 143(5.75,13.185) 144(5.25,13.185) 145(4.75,13.185) 146(4.25,13.185) 147(3.75,13.185) 148(3.25,13.185) 149(2.75,13.185) 150(2.25,13.185) 151(1.75,13.185) 152(1.25,13.185) 153(0.75,13.185) 154(0.25,13.185) 155(-0.25,13.185) 156(-0.75,13.185) 157(-1.25,13.185) 158(-1.75,13.185) 159(-2.25,13.185) 160(-2.75,13.185) 161(-3.25,13.185) 162(-3.75,13.185) 163(-4.25,13.185) 164(-4.75,13.185) 165(-5.25,13.185) 166(-5.75,13.185) 167(-6.25,13.185) 168(-6.75,13.185) 169(-7.25,13.185) 170(-7.75,13.185) 171(-8.25,13.185) 172(-8.75,13.185) 173(-9.25,13.185) 174(-9.75,13.185) 175(-10.25,13.185) 176(-10.75,13.185)
  silkscreen extent -12.67,-11.25 11.25,11.57, body extent -12.89,-12.89 12.89,12.89, height 1.55
HVQFN36_SOT1092-2DD_NXP [mm]
  rrect25% 0.96x0.255 smd paste+0 mask+0: 1(-2.817,2) 2(-2.817,1.5) 3(-2.817,1) 4(-2.817,0.5) 5(-2.817,0) 6(-2.817,-0.5) 7(-2.817,-1) 8(-2.817,-1.5) 9(-2.817,-2) 19(2.817,-2) 20(2.817,-1.5) 21(2.817,-1) 22(2.817,-0.5) 23(2.817,0) 24(2.817,0.5) 25(2.817,1) 26(2.817,1.5) 27(2.817,2)
  rrect25% 0.255x0.96 smd paste+0 mask+0: 10(-2,-2.817) 11(-1.5,-2.817) 12(-1,-2.817) 13(-0.5,-2.817) 14(0,-2.817) 15(0.5,-2.817) 16(1,-2.817) 17(1.5,-2.817) 18(2,-2.817) 28(2,2.817) 29(1.5,2.817) 30(1,2.817) 31(0.5,2.817) 32(0,2.817) 33(-0.5,2.817) 34(-1,2.817) 35(-1.5,2.817) 36(-2,2.817)
  rrect9% 4.039x4.039 smd paste-2.019 mask+0: 37(0,0)
  silkscreen extent -3.67,-3.12 3.12,3.12, body extent -3,-3 3,3, height 0.99
IND_LPS6235_COC [mil]
  rect 2x2 smd paste-1 mask-1: 1(-100,0) 2(100,0)
  round 1 smd: 1(-84.75,0) 2(84.75,0)
  Top Layer region: 39.5,82.5 39.5,130 83.5,130 130,83.5 130,-83.5 83.5,-130 39.5,-130 39.5,-82.5 82.5,-35.5 82.5,35.5
  Top Layer region: -39.5,82.5 -39.5,130 -83.5,130 -130,83.5 -130,-83.5 -83.5,-130 -39.5,-130 -39.5,-82.5 -82.5,-35.5 -82.5,35.5
  silkscreen extent -26,-124 26,124
JUMP_2 [mm]
  round 1.54 hole 0.94: 1(-1.27,0) 2(1.27,0)
  silkscreen extent -2.54,-1.27 2.54,1.27, body extent -2.54,-1.27 2.54,1.27, height 10.16
JUMP_3 [mil]
  round 60 hole 37: 1(0,0) 2(100,0) 3(-100,0)
  silkscreen extent -147,-47 147,47, body extent -150,-50 150,50, height 400
MLW14 [mil] "Header, STRT 14WAY - MLW14"
  rect 60x60 hole 37: 1(-300,-50)
  round 60 hole 37: 2(-300,50) 3(-200,-50) 4(-200,50) 5(-100,-50) 6(-100,50) 7(0,-50) 8(0,50) 9(100,-50) 10(100,50) 11(200,-50) 12(200,50) 13(300,-50) 14(300,50)
  silkscreen extent -505,-175 505,175, body extent -498,-179 498,191, height 346
"MTConn GH 8pin" [mm]
  round 1.85 hole 1.6 paste-2539.97: 1(-12.525,-3.05) 1(-9.975,-3.05) 2(-12.525,3.95) 2(-9.975,3.95) 3(-5.025,-3.05) 3(-2.475,-3.05) 4(-5.025,3.975) 4(-2.475,3.975) 5(2.475,-3.05) 5(5.025,-3.05) 6(2.475,3.95) 6(5.025,3.95) 7(9.975,-3.05) 7(12.525,-3.05) 8(9.975,3.95) 8(12.525,3.95)
  rrect80% 5.55x1.85 smd paste-2539.97: 1(-11.25,-3.05) 2(-11.25,3.95) 3(-3.75,-3.05) 4(-3.75,3.975) 5(3.75,-3.05) 6(3.75,3.95) 7(11.25,-3.05) 8(11.25,3.95)
  rrect80% 5.55x1.85 smd far side paste-2539.97: 1(-11.25,-3.05) 2(-11.25,3.95) 3(-3.75,-3.05) 4(-3.75,3.975) 5(3.75,-3.05) 6(3.75,3.95) 7(11.25,-3.05) 8(11.25,3.95)
  body extent -22.5,-10.15 22.5,10.15, height 20.7
"MTConn Power Tower M5" [mm] "M5 screw connector with protector"
  round 1.85 hole 1.45 paste-2539.97: 1(-3.795,-3.809) 1(-3.795,-1.269) 1(-3.795,1.271) 1(-3.795,3.811) 1(-1.255,-3.809) 1(-1.255,-1.269) 1(-1.255,1.271) 1(-1.255,3.811) 1(1.285,-3.809) 1(1.285,-1.269) 1(1.285,1.271) 1(1.285,3.811) 1(3.825,-3.809) 1(3.825,-1.269) 1(3.825,1.271) 1(3.825,3.811)
  rect 10x10 smd paste-2539.97: 1(0,0)
  rect 10x10 smd far side paste-2539.97: 1(0,0)
  body extent -9,-9 9,9, height 14.5
"MTConn Power Tower M6" [mm]
  round 1.85 hole 1.45 paste-2539.97: 1(-5.08,0) 1(-5.08,-5.08) 1(-5.08,-2.54) 1(-5.08,2.54) 1(-5.08,5.08) 1(-2.54,5.08) 1(-2.54,-2.54) 1(-2.54,0) 1(-2.54,2.54) 1(-2.54,-5.08) 1(0,5.08) 1(0,2.54) 1(0,0) 1(0,-2.54) 1(0,-5.08) 1(2.54,5.08) 1(2.54,-2.54) 1(2.54,0) 1(2.54,2.54) 1(2.54,-5.08) 1(5.08,-5.08) 1(5.08,-2.54) 1(5.08,2.54) 1(5.08,5.08) 1(5.08,0)
  rect 14x14 smd paste-2539.97: 1(0,0)
  rect 14x14 smd far side paste-2539.97: 1(0,0)
  body extent -12.5,-12.5 12.5,12.5, height 22.5
"MTConn Power Tower M8" [mm]
  round 1.85 hole 1.45 paste-2539.97: 1(-5.08,0) 1(-5.08,-5.08) 1(-5.08,-2.54) 1(-5.08,2.54) 1(-5.08,5.08) 1(-2.54,5.08) 1(-2.54,-2.54) 1(-2.54,0) 1(-2.54,2.54) 1(-2.54,-5.08) 1(0,5.08) 1(0,2.54) 1(0,0) 1(0,-2.54) 1(0,-5.08) 1(2.54,5.08) 1(2.54,-2.54) 1(2.54,0) 1(2.54,2.54) 1(2.54,-5.08) 1(5.08,-5.08) 1(5.08,-2.54) 1(5.08,2.54) 1(5.08,5.08) 1(5.08,0)
  rect 14x14 smd paste-2539.97: 1(0,0)
  rect 14x14 smd far side paste-2539.97: 1(0,0)
  body extent -12.5,-12.5 12.5,12.5, height 22.5
Pick_place_mark [mm] "PCB mark for pick and place machine"
  round 2 smd mask+1: 0(0,0)
  Top Layer pour cut-out: -2,0 -1.848,0.765 -1.414,1.414 -0.765,1.848 0,2 0,2 0.765,1.848 1.414,1.414 1.848,0.765 2,0 2,0 2.008,-0.008 1.856,-0.774 1.422,-1.422 0.774,-1.856 0.008,-2.008 0.008,-2.008 0,-2 -0.765,-1.848 -1.414,-1.414 -1.848,-0.765 -2,0
PIN [mil]
  round 60 hole 37: 1(0,0)
  silkscreen extent -46,-46 46,46, body extent -50,-50 50,50, height 400
Powerflat_5x6_Single_island [mm]
  round 0.025 smd paste-2539.97: D(2.507,0)
  rect 2.25x0.65 smd: G(-2.022,-1.905) S(-2.022,-0.635) S(-2.022,0.635) S(-2.022,1.905)
  Top Layer region: 2.64,-3.4 3.44,-3.4 3.44,-2.3 5.015,-2.3 5.015,-1.575 3.9,-1.575 3.9,-0.95 5.015,-0.95 5.015,-0.31 3.9,-0.31 3.9,0.31 5.015,0.31 5.015,0.95 3.9,0.95 3.9,1.575 5.015,1.575 5.015,2.3 3.44,2.3 3.44,3.4 2.64,3.4 2.64,2.3 0.99,2.3 0.99,3.4 0.19,3.4 0.19,2.3 0,2.3 0,-2.3 0.19,-2.3 0.19,-3.4 0.99,-3.4 0.99,-2.3 2.64,-2.3
  silkscreen extent -2.55,-2.7 4.13,3.27, body extent -2.07,-2.6 4.08,2.6, height 0.99
"PQFN 7x8.5" [mm]
  rrect10% 8.745x3.2 smd paste-2539.97: 0(3.5,-3.06)
  oval 1.4x0.3 smd: 1(7.17,-7.636) 2(7.17,-6.986) 3(7.17,-6.336) 4(7.17,-5.686) 7(-0.17,-5.686) 8(-0.17,-6.336) 9(-0.17,-6.986) 10(-0.17,-7.636)
  rrect20% 2.82x1.62 smd paste-2539.97: 5(5.198,-0.12) 6(1.802,-0.12)
  oval 0.3x1.4 smd: 11(1.225,-8.68) 12(1.875,-8.68) 13(2.526,-8.68) 14(3.176,-8.68) 15(3.824,-8.68) 16(4.475,-8.68) 17(5.124,-8.68) 18(5.775,-8.68)
  rrect10% 4.9x2.4 smd paste-2539.97: 19(3.5,-6.36)
  silkscreen extent 0,-8.51 7.45,-0.01, body extent 0,-8.51 7,-0.01, height 0.92
QFN6x6_VN9D30_STM [mm]
  rrect10% 3.912x3.912 smd paste-2539.97: 0(0,0)
  rrect50% 1.5x0.254 smd: 1(-3.044,1.75) 2(-3.044,1.25) 3(-3.044,0.75) 4(-3.044,0.25) 5(-3.044,-0.25) 6(-3.044,-0.75) 7(-3.044,-1.25) 8(-3.044,-1.75) 17(3.044,-1.75) 18(3.044,-1.25) 19(3.044,-0.75) 20(3.044,-0.25) 21(3.044,0.25) 22(3.044,0.75) 23(3.044,1.25) 24(3.044,1.75)
  rrect50% 0.7x0.7 smd: 1(-2.642,1.5) 3(-2.642,0.5) 21(2.642,0.5) 23(2.642,1.5) 25(1.5,2.635) 27(0.5,2.635) 29(-0.5,2.635) 31(-1.501,2.635)
  rrect50% 0.254x1.5 smd: 9(-1.75,-3.044) 10(-1.25,-3.044) 11(-0.75,-3.044) 12(-0.25,-3.044) 13(0.25,-3.044) 14(0.75,-3.044) 15(1.25,-3.044) 16(1.75,-3.044) 25(1.75,3.044) 26(1.25,3.044) 27(0.75,3.044) 28(0.25,3.044) 29(-0.25,3.044) 30(-0.75,3.044) 31(-1.25,3.044) 32(-1.75,3.044)
  round 0.025 smd: TAB(-2.642,-2.45) TAB(-2.642,2.438) TAB(2.642,-2.45) TAB(2.642,2.438)
  Top Layer region: 2.92,2.286 2.363,2.286 2.333,2.292 2.308,2.308 2.292,2.333 2.286,2.363 2.286,2.363 2.286,2.926 2.291,2.953 2.307,2.976 2.33,2.992 2.358,2.997 2.358,2.997 2.503,2.997 2.536,2.99 2.565,2.971 2.584,2.943 2.591,2.909 2.591,2.909 2.591,2.621 2.593,2.609 2.6,2.6 2.609,2.593 2.621,2.591 2.621,2.591 2.934,2.591 2.958,2.586 2.979,2.572 2.992,2.552 2.997,2.528 2.997,2.528 2.997,2.363 2.991,2.334 2.975,2.309 2.95,2.292 2.92,2.286
  Top Layer region: -2.92,2.286 -2.363,2.286 -2.333,2.292 -2.308,2.308 -2.292,2.333 -2.286,2.363 -2.286,2.363 -2.286,2.926 -2.291,2.953 -2.307,2.976 -2.33,2.992 -2.358,2.997 -2.358,2.997 -2.503,2.997 -2.536,2.99 -2.565,2.971 -2.584,2.943 -2.591,2.909 -2.591,2.909 -2.591,2.621 -2.593,2.609 -2.6,2.6 -2.609,2.593 -2.621,2.591 -2.621,2.591 -2.934,2.591 -2.958,2.586 -2.979,2.572 -2.992,2.552 -2.997,2.528 -2.997,2.528 -2.997,2.363 -2.991,2.334 -2.975,2.309 -2.95,2.292 -2.92,2.286
  Top Layer region: -2.92,-2.297 -2.363,-2.297 -2.333,-2.303 -2.308,-2.32 -2.292,-2.345 -2.286,-2.374 -2.286,-2.374 -2.286,-2.937 -2.291,-2.964 -2.307,-2.987 -2.33,-3.003 -2.358,-3.008 -2.358,-3.008 -2.503,-3.008 -2.536,-3.002 -2.565,-2.983 -2.584,-2.954 -2.591,-2.92 -2.591,-2.92 -2.591,-2.632 -2.593,-2.621 -2.6,-2.611 -2.609,-2.604 -2.621,-2.602 -2.621,-2.602 -2.934,-2.602 -2.958,-2.597 -2.979,-2.584 -2.992,-2.563 -2.997,-2.539 -2.997,-2.539 -2.997,-2.374 -2.991,-2.345 -2.975,-2.32 -2.95,-2.303 -2.92,-2.297
  Top Layer region: 2.92,-2.297 2.363,-2.297 2.333,-2.303 2.308,-2.32 2.292,-2.345 2.286,-2.374 2.286,-2.374 2.286,-2.937 2.291,-2.964 2.307,-2.987 2.33,-3.003 2.358,-3.008 2.358,-3.008 2.503,-3.008 2.536,-3.002 2.565,-2.983 2.584,-2.954 2.591,-2.92 2.591,-2.92 2.591,-2.632 2.593,-2.621 2.6,-2.611 2.609,-2.604 2.621,-2.602 2.621,-2.602 2.934,-2.602 2.958,-2.597 2.979,-2.584 2.992,-2.563 2.997,-2.539 2.997,-2.539 2.997,-2.374 2.991,-2.345 2.975,-2.32 2.95,-2.303 2.92,-2.297
  silkscreen extent -3.81,-3.12 3.12,3.12, body extent -3,-3 3,3, height 0.5
QFN32_5X5MM_STM [mm]
  rrect30% 0.805x0.249 smd paste+0 mask+0: 1(-2.477,1.75) 2(-2.477,1.25) 3(-2.477,0.75) 4(-2.477,0.25) 5(-2.477,-0.25) 6(-2.477,-0.75) 7(-2.477,-1.25) 8(-2.477,-1.75) 17(2.477,-1.75) 18(2.477,-1.25) 19(2.477,-0.75) 20(2.477,-0.25) 21(2.477,0.25) 22(2.477,0.75) 23(2.477,1.25) 24(2.477,1.75)
  rrect30% 0.249x0.805 smd paste+0 mask+0: 9(-1.75,-2.477) 10(-1.25,-2.477) 11(-0.75,-2.477) 12(-0.25,-2.477) 13(0.25,-2.477) 14(0.75,-2.477) 15(1.25,-2.477) 16(1.75,-2.477) 25(1.75,2.477) 26(1.25,2.477) 27(0.75,2.477) 28(0.25,2.477) 29(-0.25,2.477) 30(-0.75,2.477) 31(-1.25,2.477) 32(-1.75,2.477)
  rrect10% 3.7x3.7 smd paste-1.837 mask+0: 33(0,0)
  silkscreen extent -3.2,-2.63 2.63,3.2, body extent -2.58,-2.58 2.58,2.58, height 1.65
QFN32L_5x5_STM-M#1 [mm]
  rrect50% 1.25x0.255 smd mask+0.05: 1(-2.677,1.75) 8(-2.677,-1.75) 17(2.677,-1.75) 24(2.677,1.75)
  rrect50% 1.3x0.255 smd mask+0.05: 2(-2.652,1.25) 3(-2.652,0.75) 4(-2.652,0.25) 5(-2.652,-0.25) 6(-2.652,-0.75) 7(-2.652,-1.25) 18(2.652,-1.25) 19(2.652,-0.75) 20(2.652,-0.25) 21(2.652,0.25) 22(2.652,0.75) 23(2.652,1.25)
  rrect50% 0.255x1.25 smd mask+0.05: 9(-1.75,-2.677) 16(1.75,-2.648) 25(1.75,2.677) 32(-1.75,2.677)
  rrect50% 0.255x1.3 smd mask+0.05: 10(-1.25,-2.652) 11(-0.75,-2.652) 12(-0.25,-2.652) 13(0.25,-2.652) 14(0.75,-2.652) 15(1.25,-2.652) 26(1.25,2.652) 27(0.75,2.652) 28(0.25,2.652) 29(-0.25,2.652) 30(-0.75,2.652) 31(-1.25,2.652)
  rrect10% 3.6x3.6 smd paste-1.791 mask+0.05: 33(0,0)
  silkscreen extent -3.29,-2.63 2.63,2.63, body extent -2.5,-2.5 2.5,2.5, height 0.99
QFN32L_5x5_STM-M#2 [mm]
  rrect50% 1.25x0.255 smd mask+0.05: 1(-2.677,1.75) 8(-2.677,-1.75) 17(2.677,-1.75) 24(2.677,1.75)
  rrect50% 1.3x0.255 smd mask+0.05: 2(-2.652,1.25) 3(-2.652,0.75) 4(-2.652,0.25) 5(-2.652,-0.25) 6(-2.652,-0.75) 7(-2.652,-1.25) 18(2.652,-1.25) 19(2.652,-0.75) 20(2.652,-0.25) 21(2.652,0.25) 22(2.652,0.75) 23(2.652,1.25)
  rrect50% 0.255x1.25 smd mask+0.05: 9(-1.75,-2.677) 16(1.75,-2.648) 25(1.75,2.677) 32(-1.75,2.677)
  rrect50% 0.255x1.3 smd mask+0.05: 10(-1.25,-2.652) 11(-0.75,-2.652) 12(-0.25,-2.652) 13(0.25,-2.652) 14(0.75,-2.652) 15(1.25,-2.652) 26(1.25,2.652) 27(0.75,2.652) 28(0.25,2.652) 29(-0.25,2.652) 30(-0.75,2.652) 31(-1.25,2.652)
  rrect10% 3.5x3.5 smd paste-1.791 mask+0.05: 33(0,0)
  silkscreen extent -3.29,-2.63 2.63,2.63, body extent -2.5,-2.5 2.5,2.5, height 0.99
R0603_3JUMP [mm] "Threeway jumper for a 0603 resistor"
  rrect25% 0.9x0.95 smd: 1(0.725,0) 2(-0.825,0) 3(2.325,0)
  silkscreen extent -0.19,-0.51 1.69,0.51, body extent -0.85,-0.4 0.85,0.4, height 0.56
R0603_round [mm] "Resistor 0603; Body 1.6 x 0.8 mm (LxW typ); IPC_7351 nominal"
  rrect25% 0.9x0.95 smd: 1(-0.775,0) 2(0.775,0)
  silkscreen extent -0.14,-0.51 0.14,0.51, body extent -0.85,-0.4 0.85,0.4, height 0.56
R0805_ROUND [mm] "Resistor SMD 0805; IPC_7351 nominal"
  rrect25% 1.025x1.4 smd: 1(-1.143,0) 2(1.143,0)
  silkscreen extent -0.23,-0.73 0.23,0.73, body extent -1,-0.63 1,0.63, height 0.5
"R Shunt 3921" [mm] "Shunt Resistor; Body 10 x 5.2 mm (LxW typ)"
  rect 3x2.6 smd: 1(-4.25,-1.95) 1(-4.25,1.95) 2(4.25,-1.95) 2(4.25,1.95)
  rect 3x0.5 smd: 3(-4.25,0) 4(4.25,0)
  silkscreen extent -6,-3.5 6,3.5, body extent -5,-2.6 5,2.6, height 0.88
"R Shunt 5930" [mm] "Shunt Resistor; Body 6.3 x 3.2 mm (LxW typ)"
  rect 5.5x3.75 smd: 1(-5.5,-2.5) 1(-5.5,2.5) 2(5.5,-2.5) 2(5.5,2.5)
  rect 5.5x0.5 smd: 3(-5.5,0) 4(5.5,0)
  silkscreen extent -8.6,-4.7 8.6,4.7, body extent -7.5,-3.88 7.5,3.87, height 1.92
Sloupek [mm]
  round 4.5 hole 3.2: 1(0,0)
  silkscreen extent -2.98,-2.98 2.98,2.98, body extent -3,-3 3,3, height 2.48
SMC [mm]
  rect 1.54x3.15 smd: A(-3.285,0) C(3.285,0)
  silkscreen extent -4.55,-1.85 4.66,1.85, body extent -3.95,-3 3.95,3, height 2.13
SOD123FLAT_STM [mil]
  rrect25% 41x39 smd paste+0 mask+0: A(-60.5,0) C(60.5,0)
  silkscreen extent -58,-41 58,41, body extent -73,-36 73,36, height 43
SOD128FLAT_STM [mil]
  rrect25% 40.87x71 smd paste+0 mask+0: A(-81.94,0) C(81.94,0)
  silkscreen extent -82,-54 82,54, body extent -94,-49 94,49, height 41
SOT23 [mm]
  rect 1x1.6 smd: 1(0,0) 2(1.905,0) 3(0.94,2.134)
  silkscreen extent -0.18,0.15 2.06,1.55, body extent -0.48,-0.31 2.44,2.24, height 0.94
SOT323-3L_STM [mil]
  rect 34.28x16 smd paste+0 mask+0: 1(-43.64,25.59) 2(-43.64,-25.59) 3(43.64,0)
  silkscreen extent -59,-48 32,55, body extent -47,-44 47,44, height 43
WE-MAPI_5030 [mm] "SMD Power Inductor, 2-leads, body 5.6x5.6mm"
  rect 1.7x5.6 smd: 1(-1.95,0) 2(1.95,0)
  Top Layer keep-out region: -1.1,2.8 1.1,2.8 1.1,-2.8 -1.1,-2.8
  silkscreen extent -2.13,-2.8 0.75,3.37, body extent -2.7,-2.7 2.7,2.7, height 3.1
